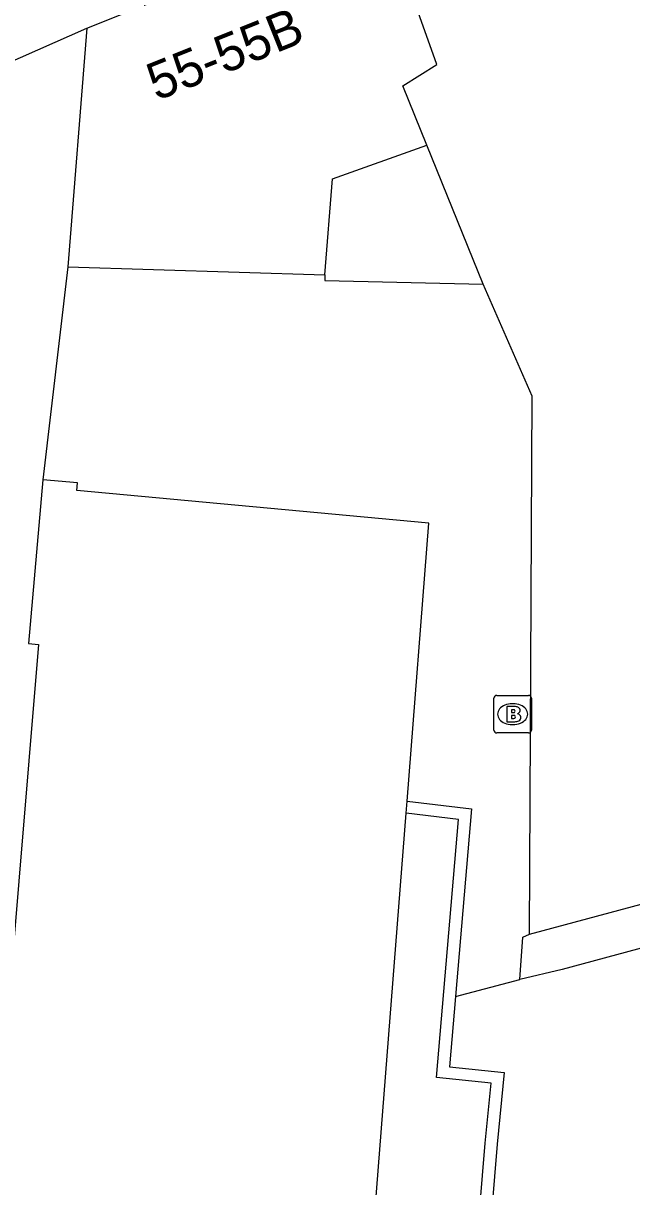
# Model space of a CAD drawing. Extents: x 160664 to 161506, y 382245 to 383288.
# Drawn here: x 161158.3 to 161174.51, y 382928.02 to 382959.02 of the extents above; entities that cross this region are included whole.
import ezdxf

# ---------------------------------------------------------------- set-up
doc = ezdxf.new("R2010")
doc.units = 0
for name, color, linetype in [('IMGEO_Brandkraan', 7, 'Continuous'), ('IMGEO_Muur', 7, 'Continuous'), ('IMGEO_Pand', 7, 'Continuous'), ('IMGEO_Pand_nummerreeks', 7, 'Continuous'), ('IMGEO_Rijbaan_lokaal_open', 7, 'Continuous'), ('IMGEO_Voetpad_open', 7, 'Continuous')]:
    doc.layers.add(name, color=color, linetype=linetype)

msp = doc.modelspace()

# ---------------------------------------------------------------- linework, layer by layer
at = {"layer": 'IMGEO_Brandkraan'}
for p, q in [((161170.839, 382940.187), (161170.839, 382941.039)), ((161170.914, 382941.113), (161171.766, 382941.113)), ((161171.84, 382941.039), (161171.84, 382940.187)), ((161171.327, 382940.893), (161171.352, 382940.893)), ((161171.35, 382940.333), (161171.325, 382940.333)), ((161171.766, 382940.113), (161170.914, 382940.113))]:
    msp.add_line(p, q, dxfattribs=at)
for points in [[(161170.839, 382940.187), (161170.839, 382941.039)], [(161170.914, 382941.113), (161171.766, 382941.113)], [(161171.84, 382941.039), (161171.84, 382940.187)], [(161171.187, 382940.813), (161171.187, 382940.413), (161171.4, 382940.413)], [(161171.418, 382940.813), (161171.187, 382940.813)], [(161171.366, 382940.732), (161171.312, 382940.732), (161171.312, 382940.656)], [(161171.312, 382940.656), (161171.365, 382940.656)], [(161171.374, 382940.58), (161171.312, 382940.58), (161171.312, 382940.499)], [(161171.312, 382940.499), (161171.374, 382940.499)], [(161171.766, 382940.113), (161170.914, 382940.113)]]:
    msp.add_lwpolyline(points, dxfattribs=at)
for centre, radius, start, end in [((161170.916, 382941.037), 0.0765, 91.552, 178.448), ((161170.916, 382941.037), 0.0765, 91.552, 178.448), ((161171.764, 382941.037), 0.0765, 1.552, 88.448), ((161171.764, 382941.037), 0.0765, 1.552, 88.448), ((161171.367, 382940.694), 0.0379, 267.8285, 90.9355), ((161171.422, 382940.668), 0.145, 59.4692, 91.5367), ((161171.447, 382940.715), 0.0922, 285.5137, 58.1501), ((161171.452, 382940.523), 0.105, 301.3115, 78.989), ((161171.375, 382940.539), 0.0404, 269.8759, 90.5077), ((161171.406, 382940.664), 0.251, 268.6676, 293.5347), ((161170.916, 382940.189), 0.0765, 181.552, 268.448), ((161170.916, 382940.189), 0.0765, 181.552, 268.448), ((161171.764, 382940.189), 0.0765, 271.552, 358.448), ((161171.764, 382940.189), 0.0765, 271.552, 358.448)]:
    msp.add_arc(centre, radius, start, end, dxfattribs=at)
for centre, major_axis, ratio, start_param, end_param in [((161171.326, 382940.613), (-0.387, 0.002), 0.722429, 4.712389, 7.853982), ((161171.351, 382940.613), (-0.39, 0.002), 0.717154, 1.570796, 4.712389)]:
    msp.add_ellipse(centre, major_axis=major_axis, ratio=ratio, start_param=start_param, end_param=end_param, dxfattribs=at)
at = {"layer": 'IMGEO_Muur'}
for points in [[(161168.527, 382938.298), (161170.242, 382938.092), (161169.816, 382933.09)], [(161166.726, 382889.033), (161166.405, 382889.176), (161168.612, 382915.876), (161169.505, 382915.825), (161170.605, 382929.186), (161170.764, 382930.783), (161169.311, 382930.933), (161169.897, 382937.811), (161168.502, 382937.978)], [(161169.816, 382933.09), (161169.657, 382931.219), (161171.114, 382931.069), (161170.924, 382929.16), (161169.798, 382915.487), (161168.905, 382915.539), (161166.744, 382889.392), (161180.917, 382884.147)]]:
    msp.add_lwpolyline(points, dxfattribs=at)
at = {"layer": 'IMGEO_Pand'}
for points in [[(161159.988, 382958.892), (161168.368, 382962.246)], [(161169.049, 382955.774), (161168.409, 382957.349), (161169.321, 382957.921), (161168.146, 382961.213), (161168.718, 382961.407), (161168.368, 382962.246)], [(161159.988, 382958.892), (161159.484, 382952.531)], [(161166.338, 382952.318), (161166.539, 382954.875), (161169.049, 382955.774)], [(161170.555, 382952.072), (161169.049, 382955.774)], [(161159.484, 382952.531), (161166.338, 382952.318)], [(161166.338, 382952.318), (161166.334, 382952.168), (161170.555, 382952.072)], [(161171.788, 382934.751), (161171.864, 382949.081), (161170.555, 382952.072)], [(161158.817, 382946.853), (161158.437, 382942.495), (161158.706, 382942.472), (161154.24, 382888.931), (161153.961, 382888.956), (161153.791, 382887.103), (161154.696, 382885.725), (161153.579, 382885.003), (161154.356, 382883.802), (161153.695, 382883.381), (161156.544, 382878.905)], [(161168.527, 382938.298), (161169.106, 382945.701), (161159.727, 382946.576), (161159.744, 382946.775), (161158.817, 382946.853)], [(161168.502, 382937.978), (161168.527, 382938.298)], [(161166.726, 382889.033), (161164.685, 382889.202), (161168.502, 382937.978)], [(161171.788, 382934.751), (161178.465, 382936.543)]]:
    msp.add_lwpolyline(points, dxfattribs=at)
at = {"layer": 'IMGEO_Rijbaan_lokaal_open'}
for points in [[(161159.484, 382952.531), (161158.817, 382946.853)], [(161171.527, 382933.542), (161171.608, 382934.674), (161171.788, 382934.751)], [(161169.816, 382933.09), (161171.527, 382933.542)]]:
    msp.add_lwpolyline(points, dxfattribs=at)
at = {"layer": 'IMGEO_Voetpad_open'}
for points in [[(161140.009, 382950.063), (161159.988, 382958.892)], [(161187.273, 382937.752), (161172.658, 382933.814), (161171.527, 382933.542)]]:
    msp.add_lwpolyline(points, dxfattribs=at)

# ---------------------------------------------------------------- texts
at = {"layer": 'IMGEO_Pand_nummerreeks'}
msp.add_text('55-55B', height=1, rotation=21.8125, dxfattribs=at).set_placement((161161.85, 382956.945))

doc.saveas('drawing.dxf')
